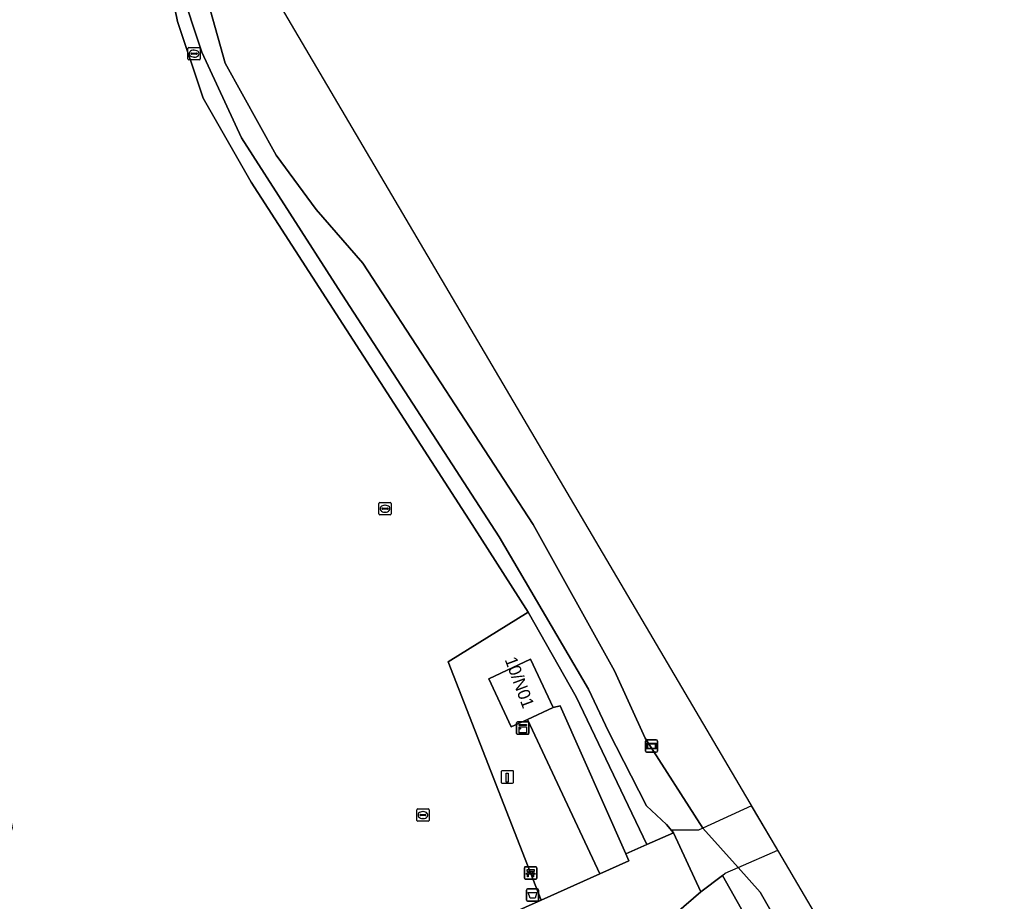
# Model space of a CAD drawing. Extents: x 160203 to 161530, y 379528 to 381797.
# Drawn here: x 161135.9 to 161216, y 379719.5 to 379790.9 of the extents above; entities that cross this region are included whole.
import ezdxf

# ---------------------------------------------------------------- set-up
doc = ezdxf.new("R2010")
doc.units = 0
for name, color, linetype in [('IMGEO_Afvalbak', 7, 'Continuous'), ('IMGEO_Bank', 7, 'Continuous'), ('IMGEO_Dek', 7, 'Continuous'), ('IMGEO_Fietspad_gesloten', 7, 'Continuous'), ('IMGEO_Fietspad_open', 7, 'Continuous'), ('IMGEO_Gemengd_bos', 7, 'Continuous'), ('IMGEO_Grasland_overig', 7, 'Continuous'), ('IMGEO_Groenvoorziening', 7, 'Continuous'), ('IMGEO_Hek', 7, 'Continuous'), ('IMGEO_Kast', 7, 'Continuous'), ('IMGEO_Loofbos', 7, 'Continuous'), ('IMGEO_Oever', 7, 'Continuous'), ('IMGEO_Paal', 7, 'Continuous'), ('IMGEO_Pand', 7, 'Continuous'), ('IMGEO_Pand_nummerreeks', 7, 'Continuous'), ('IMGEO_Rioolput', 7, 'Continuous'), ('IMGEO_Verklikker', 7, 'Continuous'), ('IMGEO_Voetpad_open', 7, 'Continuous'), ('IMGEO_Waterloop', 7, 'Continuous')]:
    doc.layers.add(name, color=color, linetype=linetype)

msp = doc.modelspace()

# ---------------------------------------------------------------- linework, layer by layer
at = {"layer": 'IMGEO_Afvalbak'}
for p, q in [((161176.95, 379719.58), (161176.95, 379720.38)), ((161176.95, 379720.38), (161176.95, 379719.58)), ((161177.05, 379720.48), (161177.84, 379720.48)), ((161177.84, 379720.48), (161177.05, 379720.48)), ((161177.94, 379720.38), (161177.94, 379719.58)), ((161177.94, 379719.58), (161177.94, 379720.38)), ((161177.84, 379719.48), (161177.05, 379719.48)), ((161177.05, 379719.48), (161177.84, 379719.48))]:
    msp.add_line(p, q, dxfattribs=at)
msp.add_lwpolyline([(161177.093, 379720.194), (161177.797, 379720.194), (161177.648, 379719.724), (161177.242, 379719.724), (161177.093, 379720.194)], dxfattribs=at)
for centre, start, end in [((161177.05, 379720.38), 90, 180), ((161177.05, 379720.38), 90, 180), ((161177.84, 379720.38), 0, 90), ((161177.84, 379720.38), 360, 90), ((161177.05, 379719.58), 180, 270), ((161177.05, 379719.58), 180, 270), ((161177.84, 379719.58), 270, 0), ((161177.84, 379719.58), 270, 0)]:
    msp.add_arc(centre, 0.1, start, end, dxfattribs=at)
at = {"layer": 'IMGEO_Bank'}
for p, q in [((161176.788, 379721.342), (161176.788, 379722.183)), ((161176.788, 379722.183), (161176.788, 379721.342)), ((161176.863, 379722.267), (161177.704, 379722.267)), ((161177.704, 379722.267), (161176.863, 379722.267)), ((161177.485, 379721.665), (161177.092, 379721.665)), ((161177.097, 379721.773), (161177.097, 379721.879)), ((161177.141, 379721.879), (161177.141, 379721.773)), ((161177.429, 379721.885), (161177.147, 379721.885)), ((161177.147, 379721.767), (161177.429, 379721.767)), ((161177.435, 379721.773), (161177.435, 379721.879)), ((161177.479, 379721.879), (161177.479, 379721.773)), ((161177.788, 379722.192), (161177.788, 379721.351)), ((161177.788, 379721.351), (161177.788, 379722.192)), ((161177.713, 379721.267), (161176.872, 379721.267)), ((161176.872, 379721.267), (161177.713, 379721.267))]:
    msp.add_line(p, q, dxfattribs=at)
for points in [[(161177.035, 379721.665), (161176.893, 379721.665), (161177.005, 379721.767), (161177.091, 379721.767)], [(161177.091, 379721.885), (161177.005, 379721.885), (161177.005, 379722.046), (161177.568, 379722.046), (161177.568, 379721.885), (161177.485, 379721.885)], [(161177.085, 379721.658), (161177.085, 379721.451), (161177.042, 379721.451), (161177.042, 379721.658)], [(161177.485, 379721.767), (161177.568, 379721.767), (161177.68, 379721.665), (161177.541, 379721.665)], [(161177.535, 379721.658), (161177.535, 379721.451), (161177.491, 379721.451), (161177.491, 379721.658)]]:
    msp.add_lwpolyline(points, dxfattribs=at)
for centre, radius, start, end in [((161176.866, 379722.189), 0.0779, 92.4484, 184.28452), ((161176.866, 379722.189), 0.0779, 92.4484, 184.28452), ((161177.035, 379721.658), 0.00671, 2.89567, 87.10433), ((161177.092, 379721.658), 0.00671, 92.89567, 177.10433), ((161177.09, 379721.878), 0.00671, 2.89567, 87.10433), ((161177.09, 379721.774), 0.00671, 272.89567, 357.10433), ((161177.147, 379721.878), 0.00671, 92.89567, 177.10433), ((161177.147, 379721.774), 0.00671, 182.89567, 267.10433), ((161177.429, 379721.878), 0.00671, 2.89567, 87.10433), ((161177.429, 379721.774), 0.00671, 272.89567, 357.10433), ((161177.486, 379721.878), 0.00671, 92.89567, 177.10433), ((161177.486, 379721.774), 0.00671, 182.89567, 267.10433), ((161177.484, 379721.658), 0.00671, 2.89567, 87.10433), ((161177.541, 379721.658), 0.00671, 92.89567, 177.10433), ((161177.71, 379722.189), 0.0779, 2.4484, 94.28452), ((161177.71, 379722.189), 0.0779, 2.4484, 94.28452), ((161176.866, 379721.345), 0.0779, 182.4484, 274.28452), ((161176.866, 379721.345), 0.0779, 182.4484, 274.28452), ((161177.71, 379721.345), 0.0779, 272.4484, 4.28452), ((161177.71, 379721.345), 0.0779, 272.4484, 4.28452)]:
    msp.add_arc(centre, radius, start, end, dxfattribs=at)
at = {"layer": 'IMGEO_Dek'}
msp.add_lwpolyline([(161197.31, 379723.614), (161195.19, 379727.216), (161195.182, 379727.212), (161191.229, 379725.397), (161190.887, 379725.24), (161190.769, 379725.24), (161188.926, 379725.245), (161188.765, 379725.245), (161188.867, 379725.024), (161191.069, 379720.232), (161192.831, 379721.573), (161193.05, 379721.74), (161194.099, 379722.202), (161197.302, 379723.611)], close=True, dxfattribs=at)
at = {"layer": 'IMGEO_Fietspad_gesloten'}
msp.add_lwpolyline([(161197.31, 379723.614), (161195.19, 379727.216), (161195.182, 379727.212), (161191.229, 379725.397), (161190.887, 379725.24), (161190.769, 379725.24), (161188.926, 379725.245), (161188.765, 379725.245), (161188.867, 379725.024), (161191.069, 379720.232), (161192.831, 379721.573), (161193.05, 379721.74), (161194.099, 379722.202), (161197.302, 379723.611)], close=True, dxfattribs=at)
at = {"layer": 'IMGEO_Fietspad_open'}
msp.add_lwpolyline([(161163.158, 379708.39), (161184.518, 379718.109), (161185.75, 379715.652), (161191.069, 379720.232), (161188.867, 379725.024), (161186.707, 379724.077), (161185, 379723.328), (161185.257, 379722.747), (161182.898, 379721.692), (161178.144, 379719.567), (161166.237, 379714.245), (161163.137, 379712.76), (161162.029, 379712.153)], dxfattribs=at)
at = {"layer": 'IMGEO_Gemengd_bos'}
msp.add_lwpolyline([(161154.668, 379777.718), (161150.778, 379784.521), (161148.701, 379790.741), (161147.522, 379796.416), (161147.053, 379802.179), (161147.26, 379805.232), (161147.441, 379805.854), (161140.72, 379795.347), (161132.999, 379794.191), (161132.567, 379791.884), (161131.907, 379787.485), (161128.136, 379765.01), (161130.852, 379750), (161135.297, 379725.421), (161131.57, 379713.852), (161144.164, 379716.433), (161150.699, 379717.235), (161157.727, 379717.37), (161166.237, 379714.245), (161178.144, 379719.567), (161170.609, 379738.874), (161177.102, 379742.887), (161172.567, 379750)], close=True, dxfattribs=at)
at = {"layer": 'IMGEO_Grasland_overig'}
msp.add_lwpolyline([(161147.522, 379796.416), (161148.701, 379790.741), (161150.778, 379784.521), (161154.668, 379777.718), (161172.567, 379750), (161177.102, 379742.887), (161180.991, 379736.022), (161186.707, 379724.077), (161188.867, 379725.024), (161188.29, 379725.692), (161186.665, 379727.194), (161183.593, 379733.239), (161181.975, 379736.65), (161174.736, 379748.988), (161161.701, 379769.095), (161153.888, 379781.309), (161150.67, 379788.236), (161148.887, 379793.652)], dxfattribs=at)
at = {"layer": 'IMGEO_Groenvoorziening'}
msp.add_lwpolyline([(161186.707, 379724.077), (161180.991, 379736.022), (161177.102, 379742.887), (161170.609, 379738.874), (161178.144, 379719.567), (161182.898, 379721.692), (161177.03, 379734.209), (161175.727, 379733.598), (161173.9, 379737.495), (161177.277, 379739.079), (161179.104, 379735.182), (161179.697, 379735.304), (161185, 379723.328)], close=True, dxfattribs=at)
at = {"layer": 'IMGEO_Hek'}
for points in [[(161160.654, 379825.714), (161158.373, 379822.786), (161155.224, 379818.995), (161150.141, 379812.875), (161148.443, 379809.291), (161147.441, 379805.854), (161147.26, 379805.232), (161147.053, 379802.179), (161147.522, 379796.416), (161148.701, 379790.741), (161150.778, 379784.521), (161154.668, 379777.718), (161172.567, 379750), (161177.102, 379742.887)], [(161177.102, 379742.887), (161170.609, 379738.874), (161178.144, 379719.567)], [(161195.19, 379727.216), (161195.182, 379727.212), (161191.229, 379725.397), (161190.887, 379725.24), (161190.769, 379725.24), (161188.926, 379725.245), (161188.765, 379725.245)], [(161191.069, 379720.232), (161192.831, 379721.573), (161193.05, 379721.74), (161194.099, 379722.202), (161197.302, 379723.611), (161197.31, 379723.614)]]:
    msp.add_lwpolyline(points, dxfattribs=at)
at = {"layer": 'IMGEO_Kast'}
for p, q in [((161176.158, 379733.078), (161176.158, 379733.919)), ((161176.158, 379733.919), (161176.158, 379733.078)), ((161176.233, 379734.003), (161177.074, 379734.003)), ((161177.074, 379734.003), (161176.233, 379734.003)), ((161177.158, 379733.928), (161177.158, 379733.087)), ((161177.158, 379733.087), (161177.158, 379733.928)), ((161177.083, 379733.003), (161176.242, 379733.003)), ((161176.242, 379733.003), (161177.083, 379733.003))]:
    msp.add_line(p, q, dxfattribs=at)
for points in [[(161176.353, 379733.793), (161176.953, 379733.793), (161176.953, 379733.708), (161176.353, 379733.708), (161176.353, 379733.793)], [(161176.353, 379733.618), (161176.953, 379733.618), (161176.953, 379733.129), (161176.353, 379733.129), (161176.353, 379733.618)]]:
    msp.add_lwpolyline(points, dxfattribs=at)
msp.add_circle((161176.437, 379733.467), 0.0377, dxfattribs=at)
for centre, start, end in [((161176.236, 379733.925), 92.4484, 184.28452), ((161176.236, 379733.925), 92.4484, 184.28452), ((161177.08, 379733.925), 2.4484, 94.28452), ((161177.08, 379733.925), 2.4484, 94.28452), ((161176.236, 379733.081), 182.4484, 274.28452), ((161176.236, 379733.081), 182.4484, 274.28452), ((161177.08, 379733.081), 272.4484, 4.28452), ((161177.08, 379733.081), 272.4484, 4.28452)]:
    msp.add_arc(centre, 0.0779, start, end, dxfattribs=at)
at = {"layer": 'IMGEO_Loofbos'}
msp.add_lwpolyline([(161196.148, 379715.674), (161192.831, 379721.573), (161191.069, 379720.232), (161185.75, 379715.652)], dxfattribs=at)
at = {"layer": 'IMGEO_Oever'}
for points in [[(161208.326, 379655.517), (161206.88, 379660.818), (161202.219, 379674.45), (161200.267, 379681.627), (161199.543, 379685.234), (161199.325, 379687.47), (161199.177, 379693.241), (161199.173, 379701.104), (161198.953, 379707.056), (161198.698, 379711.492), (161198.444, 379713.909), (161197.72, 379717.01), (161195.879, 379720.22), (161194.099, 379722.202), (161191.229, 379725.397), (161186.579, 379732.693), (161184.094, 379738.134), (161177.51, 379750), (161163.709, 379771.17), (161159.934, 379775.512), (161156.686, 379779.915), (161152.552, 379787.368), (161149.975, 379796.524)], [(161148.887, 379793.652), (161150.67, 379788.236), (161153.888, 379781.309), (161161.701, 379769.095), (161174.736, 379748.988), (161181.975, 379736.65), (161183.593, 379733.239), (161186.665, 379727.194), (161188.29, 379725.692), (161188.867, 379725.024), (161191.069, 379720.232), (161192.831, 379721.573), (161196.148, 379715.674), (161197.196, 379711.851), (161197.415, 379708.136), (161197.455, 379701.066), (161197.93, 379691.976), (161198.187, 379683.716), (161200.176, 379676.251), (161202.416, 379669.002), (161205.343, 379660.744), (161206.644, 379656.164)]]:
    msp.add_lwpolyline(points, dxfattribs=at)
at = {"layer": 'IMGEO_Paal'}
for p, q in [((161174.909, 379729.966), (161174.909, 379729.125)), ((161174.909, 379729.966), (161174.909, 379729.125)), ((161175.825, 379730.05), (161174.984, 379730.05)), ((161175.825, 379730.05), (161174.984, 379730.05)), ((161175.909, 379729.134), (161175.909, 379729.975)), ((161175.909, 379729.134), (161175.909, 379729.975)), ((161174.993, 379729.05), (161175.834, 379729.05)), ((161174.993, 379729.05), (161175.834, 379729.05))]:
    msp.add_line(p, q, dxfattribs=at)
msp.add_lwpolyline([(161175.324, 379729.863), (161175.484, 379729.863), (161175.484, 379729.13), (161175.324, 379729.13), (161175.324, 379729.863)], dxfattribs=at)
for centre, start, end in [((161174.987, 379729.972), 92.4484, 184.28452), ((161174.987, 379729.972), 92.4484, 184.28452), ((161175.831, 379729.972), 2.4484, 94.28452), ((161175.831, 379729.972), 2.4484, 94.28452), ((161174.987, 379729.128), 182.4484, 274.28452), ((161174.987, 379729.128), 182.4484, 274.28452), ((161175.831, 379729.128), 272.4484, 4.28452), ((161175.831, 379729.128), 272.4484, 4.28452)]:
    msp.add_arc(centre, 0.0779, start, end, dxfattribs=at)
at = {"layer": 'IMGEO_Pand'}
msp.add_lwpolyline([(161179.104, 379735.182), (161177.277, 379739.079), (161173.9, 379737.495), (161175.727, 379733.598), (161177.03, 379734.209)], close=True, dxfattribs=at)
at = {"layer": 'IMGEO_Rioolput'}
for p, q in [((161149.537, 379787.7), (161149.537, 379788.552)), ((161149.612, 379788.626), (161150.464, 379788.626)), ((161149.796, 379788.12), (161149.796, 379788.132)), ((161150.234, 379788.083), (161149.836, 379788.083)), ((161149.839, 379788.169), (161150.237, 379788.169)), ((161150.025, 379788.406), (161150.05, 379788.406)), ((161150.28, 379788.132), (161150.28, 379788.12)), ((161150.538, 379788.552), (161150.538, 379787.7)), ((161150.464, 379787.626), (161149.612, 379787.626)), ((161150.048, 379787.846), (161150.023, 379787.846)), ((161164.999, 379750.846), (161164.999, 379751.698)), ((161165.074, 379751.772), (161165.926, 379751.772)), ((161165.258, 379751.266), (161165.258, 379751.278)), ((161165.301, 379751.315), (161165.699, 379751.315)), ((161165.487, 379751.552), (161165.512, 379751.552)), ((161165.742, 379751.278), (161165.742, 379751.266)), ((161166, 379751.698), (161166, 379750.846)), ((161165.926, 379750.772), (161165.074, 379750.772)), ((161165.696, 379751.229), (161165.298, 379751.229)), ((161165.51, 379750.992), (161165.485, 379750.992)), ((161168.071, 379726.032), (161168.071, 379726.884)), ((161168.146, 379726.958), (161168.998, 379726.958)), ((161168.33, 379726.452), (161168.33, 379726.464)), ((161168.373, 379726.501), (161168.771, 379726.501)), ((161168.559, 379726.738), (161168.584, 379726.738)), ((161168.814, 379726.464), (161168.814, 379726.452)), ((161169.072, 379726.884), (161169.072, 379726.032)), ((161168.998, 379725.958), (161168.146, 379725.958)), ((161168.768, 379726.415), (161168.37, 379726.415)), ((161168.582, 379726.178), (161168.557, 379726.178))]:
    msp.add_line(p, q, dxfattribs=at)
for points in [[(161149.537, 379787.7), (161149.537, 379788.552)], [(161149.612, 379788.626), (161150.464, 379788.626)], [(161150.538, 379788.552), (161150.538, 379787.7)], [(161150.464, 379787.626), (161149.612, 379787.626)], [(161164.999, 379750.846), (161164.999, 379751.698)], [(161165.074, 379751.772), (161165.926, 379751.772)], [(161166, 379751.698), (161166, 379750.846)], [(161165.926, 379750.772), (161165.074, 379750.772)], [(161168.071, 379726.032), (161168.071, 379726.884)], [(161168.146, 379726.958), (161168.998, 379726.958)], [(161169.072, 379726.884), (161169.072, 379726.032)], [(161168.998, 379725.958), (161168.146, 379725.958)]]:
    msp.add_lwpolyline(points, dxfattribs=at)
for centre, radius, start, end in [((161149.614, 379788.55), 0.0765, 91.55205, 178.44795), ((161149.614, 379788.55), 0.0765, 91.55205, 178.44795), ((161149.836, 379788.129), 0.0403, 85.87752, 175.75265), ((161149.833, 379788.119), 0.0366, 178.93798, 274.71019), ((161150.237, 379788.126), 0.043, 264.86636, 352.45326), ((161150.241, 379788.131), 0.0386, 1.73085, 96.63898), ((161150.462, 379788.55), 0.0765, 1.55205, 88.44795), ((161150.462, 379788.55), 0.0765, 1.55205, 88.44795), ((161149.614, 379787.702), 0.0765, 181.55205, 268.44795), ((161149.614, 379787.702), 0.0765, 181.55205, 268.44795), ((161150.462, 379787.702), 0.0765, 271.55205, 358.44795), ((161150.462, 379787.702), 0.0765, 271.55205, 358.44795), ((161165.076, 379751.696), 0.0765, 91.55205, 178.44795), ((161165.076, 379751.696), 0.0765, 91.55205, 178.44795), ((161165.298, 379751.275), 0.0403, 85.87752, 175.75265), ((161165.295, 379751.265), 0.0366, 178.93798, 274.71019), ((161165.699, 379751.272), 0.043, 264.86636, 352.45326), ((161165.703, 379751.277), 0.0386, 1.73085, 96.63898), ((161165.924, 379751.696), 0.0765, 1.55205, 88.44795), ((161165.924, 379751.696), 0.0765, 1.55205, 88.44795), ((161165.076, 379750.848), 0.0765, 181.55205, 268.44795), ((161165.076, 379750.848), 0.0765, 181.55205, 268.44795), ((161165.924, 379750.848), 0.0765, 271.55205, 358.44795), ((161165.924, 379750.848), 0.0765, 271.55205, 358.44795), ((161168.148, 379726.882), 0.0765, 91.55205, 178.44795), ((161168.148, 379726.882), 0.0765, 91.55205, 178.44795), ((161168.37, 379726.461), 0.0403, 85.87752, 175.75265), ((161168.367, 379726.451), 0.0366, 178.93798, 274.71019), ((161168.771, 379726.458), 0.043, 264.86636, 352.45326), ((161168.775, 379726.463), 0.0386, 1.73085, 96.63898), ((161168.996, 379726.882), 0.0765, 1.55205, 88.44795), ((161168.996, 379726.882), 0.0765, 1.55205, 88.44795), ((161168.148, 379726.034), 0.0765, 181.55205, 268.44795), ((161168.148, 379726.034), 0.0765, 181.55205, 268.44795), ((161168.996, 379726.034), 0.0765, 271.55205, 358.44795), ((161168.996, 379726.034), 0.0765, 271.55205, 358.44795)]:
    msp.add_arc(centre, radius, start, end, dxfattribs=at)
for centre, major_axis, ratio, start_param, end_param in [((161150.024, 379788.126), (-0.387, 0.002), 0.722429, 4.712389, 7.853982), ((161150.049, 379788.126), (-0.39, 0.002), 0.717154, 1.570796, 4.712389), ((161165.486, 379751.272), (-0.387, 0.002), 0.722429, 4.712389, 7.853982), ((161165.511, 379751.272), (-0.39, 0.002), 0.717154, 1.570796, 4.712389), ((161168.558, 379726.458), (-0.387, 0.002), 0.722429, 4.712389, 7.853982), ((161168.583, 379726.458), (-0.39, 0.002), 0.717154, 1.570796, 4.712389)]:
    msp.add_ellipse(centre, major_axis=major_axis, ratio=ratio, start_param=start_param, end_param=end_param, dxfattribs=at)
at = {"layer": 'IMGEO_Verklikker'}
for p, q in [((161186.582, 379731.646), (161186.582, 379732.446)), ((161186.582, 379732.446), (161186.582, 379731.646)), ((161186.682, 379732.546), (161187.472, 379732.546)), ((161187.472, 379732.546), (161186.682, 379732.546)), ((161187.572, 379732.446), (161187.572, 379731.646)), ((161187.572, 379731.646), (161187.572, 379732.446)), ((161187.472, 379731.546), (161186.682, 379731.546)), ((161186.682, 379731.546), (161187.472, 379731.546))]:
    msp.add_line(p, q, dxfattribs=at)
for points in [[(161186.683, 379732.278), (161187.471, 379732.278), (161187.471, 379731.814), (161186.683, 379731.814), (161186.683, 379732.278)], [(161186.748, 379732.213), (161186.748, 379731.879), (161187.406, 379731.879), (161187.406, 379732.213), (161186.748, 379732.213)]]:
    msp.add_lwpolyline(points, dxfattribs=at)
for centre, start, end in [((161186.682, 379732.446), 90, 180), ((161186.682, 379732.446), 90, 180), ((161187.472, 379732.446), 0, 90), ((161187.472, 379732.446), 360, 90), ((161186.682, 379731.646), 180, 270), ((161186.682, 379731.646), 180, 270), ((161187.472, 379731.646), 270, 0), ((161187.472, 379731.646), 270, 0)]:
    msp.add_arc(centre, 0.1, start, end, dxfattribs=at)
at = {"layer": 'IMGEO_Voetpad_open'}
msp.add_lwpolyline([(161179.697, 379735.304), (161179.104, 379735.182), (161177.03, 379734.209), (161182.898, 379721.692), (161185.257, 379722.747), (161185, 379723.328)], close=True, dxfattribs=at)
at = {"layer": 'IMGEO_Waterloop'}
for points in [[(161149.975, 379796.524), (161152.552, 379787.368), (161156.686, 379779.915), (161159.934, 379775.512), (161163.709, 379771.17), (161177.51, 379750), (161184.094, 379738.134), (161186.579, 379732.693), (161191.229, 379725.397), (161194.099, 379722.202), (161195.879, 379720.22), (161197.72, 379717.01), (161198.444, 379713.909), (161198.698, 379711.492), (161198.953, 379707.056), (161199.173, 379701.104), (161199.177, 379693.241), (161199.325, 379687.47), (161199.543, 379685.234), (161200.267, 379681.627), (161202.219, 379674.45), (161206.88, 379660.818), (161208.326, 379655.517)], [(161215.793, 379540.445), (161215.793, 379540.445), (161215.973, 379545.223), (161215.97, 379546.687), (161215.905, 379643.273), (161215.91, 379649.033), (161215.728, 379652.099), (161214.352, 379660.394), (161209.697, 379673.428), (161206.253, 379684.528), (161204.37, 379711.608), (161204.369, 379711.621), (161197.651, 379723.035), (161155.607, 379794.465)]]:
    msp.add_lwpolyline(points, dxfattribs=at)

# ---------------------------------------------------------------- texts
at = {"layer": 'IMGEO_Pand_nummerreeks'}
msp.add_text('10/N01', height=1, rotation=290.40988, dxfattribs=at).set_placement((161175.18, 379739.054))

doc.saveas('drawing.dxf')
